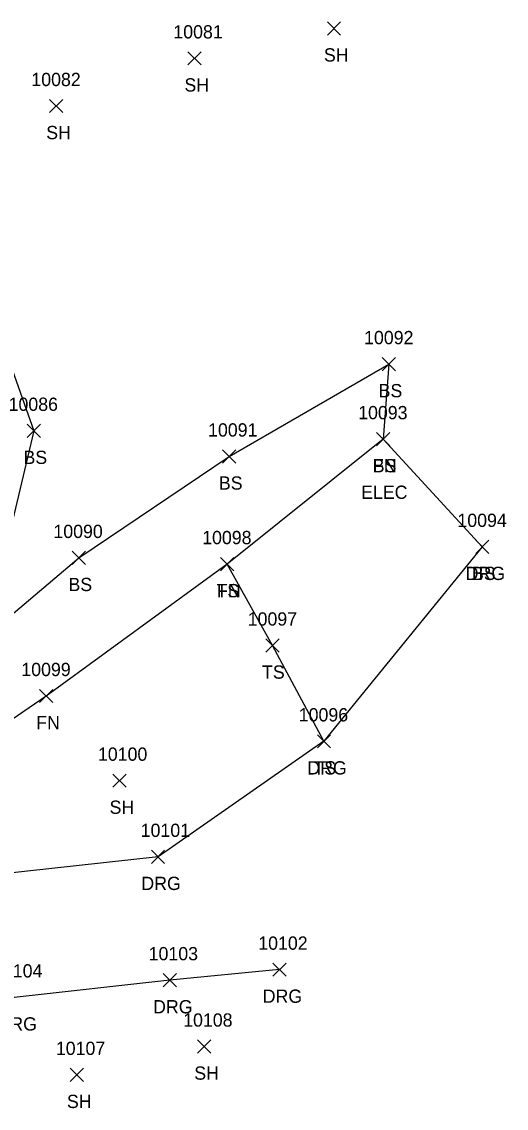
# Model space of a CAD drawing. Extents: x 1475671 to 1477951, y 592661 to 593821.
# Drawn here: x 1476962.1 to 1477035.1, y 592673.6 to 592837.4 of the extents above; entities that cross this region are included whole.
import ezdxf

# ---------------------------------------------------------------- set-up
doc = ezdxf.new("R2010")
doc.units = 0
for name, color, linetype in [('L_A', 7, 'Continuous'), ('L_C', 7, 'Continuous'), ('L_I', 7, 'Continuous'), ('L_TIC', 7, 'Continuous'), ('LELB', 7, 'Continuous'), ('LFNC', 7, 'Continuous'), ('R_A', 7, 'Continuous'), ('R_I', 7, 'Continuous'), ('R_TIC', 7, 'Continuous'), ('RDG', 7, 'Continuous')]:
    doc.layers.add(name, color=color, linetype=linetype)

msp = doc.modelspace()

# ---------------------------------------------------------------- linework, layer by layer
at = {"layer": 'L_TIC'}
for points in [[(1477008.16, 592835.38), (1477010.16, 592837.38)], [(1477010.16, 592835.38), (1477008.16, 592837.38)], [(1476987.14, 592830.86), (1476989.14, 592832.86)], [(1476989.14, 592830.86), (1476987.14, 592832.86)], [(1476966.32, 592823.68), (1476968.32, 592825.68)], [(1476968.32, 592823.68), (1476966.32, 592825.68)], [(1477016.44, 592784.78), (1477018.44, 592786.78)], [(1477018.44, 592784.78), (1477016.44, 592786.78)], [(1476962.94, 592774.73), (1476964.94, 592776.73)], [(1476964.94, 592774.73), (1476962.94, 592776.73)], [(1477015.55, 592773.47), (1477017.55, 592775.47)], [(1477017.55, 592773.47), (1477015.55, 592775.47)], [(1477015.55, 592773.47), (1477017.55, 592775.47)], [(1477017.55, 592773.47), (1477015.55, 592775.47)], [(1476992.37, 592770.86), (1476994.37, 592772.86)], [(1476994.37, 592770.86), (1476992.37, 592772.86)], [(1477030.5, 592757.24), (1477032.5, 592759.24)], [(1477032.5, 592757.24), (1477030.5, 592759.24)], [(1476969.72, 592755.57), (1476971.72, 592757.57)], [(1476971.72, 592755.57), (1476969.72, 592757.57)], [(1476992.05, 592754.64), (1476994.05, 592756.64)], [(1476994.05, 592754.64), (1476992.05, 592756.64)], [(1476992.05, 592754.64), (1476994.05, 592756.64)], [(1476994.05, 592754.64), (1476992.05, 592756.64)], [(1476998.91, 592742.37), (1477000.91, 592744.37)], [(1477000.91, 592742.37), (1476998.91, 592744.37)], [(1476964.82, 592734.76), (1476966.82, 592736.76)], [(1476966.82, 592734.76), (1476964.82, 592736.76)], [(1477006.65, 592727.93), (1477008.65, 592729.93)], [(1477008.65, 592727.93), (1477006.65, 592729.93)], [(1476975.86, 592722), (1476977.86, 592724)], [(1476977.86, 592722), (1476975.86, 592724)], [(1476988.62, 592681.93), (1476990.62, 592683.93)], [(1476990.62, 592681.93), (1476988.62, 592683.93)], [(1476969.44, 592677.66), (1476971.44, 592679.66)], [(1476971.44, 592677.66), (1476969.44, 592679.66)]]:
    msp.add_lwpolyline(points, dxfattribs=at)
at = {"layer": 'LELB'}
for points in [[(1476927.31, 592835.25), (1476952.76, 592807.27), (1476963.94, 592775.73), (1476956.5, 592744.56), (1476970.72, 592756.57), (1476993.37, 592771.86), (1477017.44, 592785.78), (1477016.55, 592774.47), (1477031.5, 592758.24)], [(1477007.65, 592728.93), (1476999.91, 592743.37), (1476993.05, 592755.64)]]:
    msp.add_lwpolyline(points, dxfattribs=at)
at = {"layer": 'LFNC'}
msp.add_lwpolyline([(1477016.55, 592774.47), (1476993.05, 592755.64), (1476965.82, 592735.76), (1476947.68, 592723.33)], dxfattribs=at)
at = {"layer": 'R_TIC'}
for points in [[(1477030.5, 592757.24), (1477032.5, 592759.24)], [(1477032.5, 592757.24), (1477030.5, 592759.24)], [(1477006.65, 592727.93), (1477008.65, 592729.93)], [(1477008.65, 592727.93), (1477006.65, 592729.93)], [(1476981.65, 592710.52), (1476983.65, 592712.52)], [(1476983.65, 592710.52), (1476981.65, 592712.52)], [(1476983.42, 592691.93), (1476985.42, 592693.93)], [(1476985.42, 592691.93), (1476983.42, 592693.93)], [(1476999.94, 592693.52), (1477001.94, 592695.52)], [(1477001.94, 592693.52), (1476999.94, 592695.52)]]:
    msp.add_lwpolyline(points, dxfattribs=at)
at = {"layer": 'RDG'}
for points in [[(1477031.5, 592758.24), (1477007.65, 592728.93), (1476982.65, 592711.52), (1476950.12, 592707.98), (1476942.58, 592713.1), (1476938.73, 592716.33)], [(1477000.94, 592694.52), (1476984.42, 592692.93), (1476960.98, 592690.34), (1476951.75, 592685.76), (1476951.31, 592685.81), (1476946.44, 592678.68)]]:
    msp.add_lwpolyline(points, dxfattribs=at)

# ---------------------------------------------------------------- texts
at = {"layer": 'L_A'}
for s, p in [('SH', (1477007.64, 592831.38)), ('SH', (1476986.63, 592826.86)), ('SH', (1476965.81, 592819.68)), ('BS', (1477015.88, 592780.78)), ('BS', (1476962.38, 592770.73)), ('BS', (1477014.99, 592769.47)), ('FN', (1477015.03, 592769.47)), ('BS', (1476991.82, 592766.86)), ('BS', (1477029.94, 592753.24)), ('BS', (1476969.16, 592751.57)), ('TS', (1476991.46, 592750.64)), ('FN', (1476991.53, 592750.64)), ('TS', (1476998.32, 592738.37)), ('FN', (1476964.3, 592730.76)), ('TS', (1477006.06, 592723.93)), ('SH', (1476975.35, 592718)), ('SH', (1476988.11, 592677.93)), ('SH', (1476968.93, 592673.66))]:
    msp.add_text(s, height=2, dxfattribs=at).set_placement(p)
at = {"layer": 'L_C'}
msp.add_text('ELEC', height=2, dxfattribs=at).set_placement((1477013.24, 592765.47))
at = {"layer": 'L_I'}
for s, p in [('10081', (1476984.96, 592834.86)), ('10082', (1476963.57, 592827.68)), ('10092', (1477013.69, 592788.78)), ('10086', (1476960.14, 592778.73)), ('10093', (1477012.8, 592777.47)), ('10093', (1477012.8, 592777.47)), ('10091', (1476990.19, 592774.86)), ('10094', (1477027.75, 592761.24)), ('10090', (1476966.89, 592759.57)), ('10098', (1476989.3, 592758.64)), ('10098', (1476989.3, 592758.64)), ('10097', (1476996.16, 592746.37)), ('10099', (1476962.06, 592738.76)), ('10096', (1477003.85, 592731.93)), ('10100', (1476973.6, 592726)), ('10108', (1476986.44, 592685.93)), ('10107', (1476967.26, 592681.66))]:
    msp.add_text(s, height=2, dxfattribs=at).set_placement(p)
at = {"layer": 'R_A'}
for p in [(1477028.99, 592753.24), (1477005.14, 592723.93), (1476980.14, 592706.52), (1476998.42, 592689.52), (1476981.91, 592687.93), (1476958.47, 592685.34)]:
    msp.add_text('DRG', height=2, dxfattribs=at).set_placement(p)
at = {"layer": 'R_I'}
for s, p in [('10094', (1477027.75, 592761.24)), ('10096', (1477003.85, 592731.93)), ('10101', (1476980.04, 592714.52)), ('10102', (1476997.75, 592697.52)), ('10103', (1476981.24, 592695.93)), ('10104', (1476957.8, 592693.34))]:
    msp.add_text(s, height=2, dxfattribs=at).set_placement(p)

doc.saveas('drawing.dxf')
